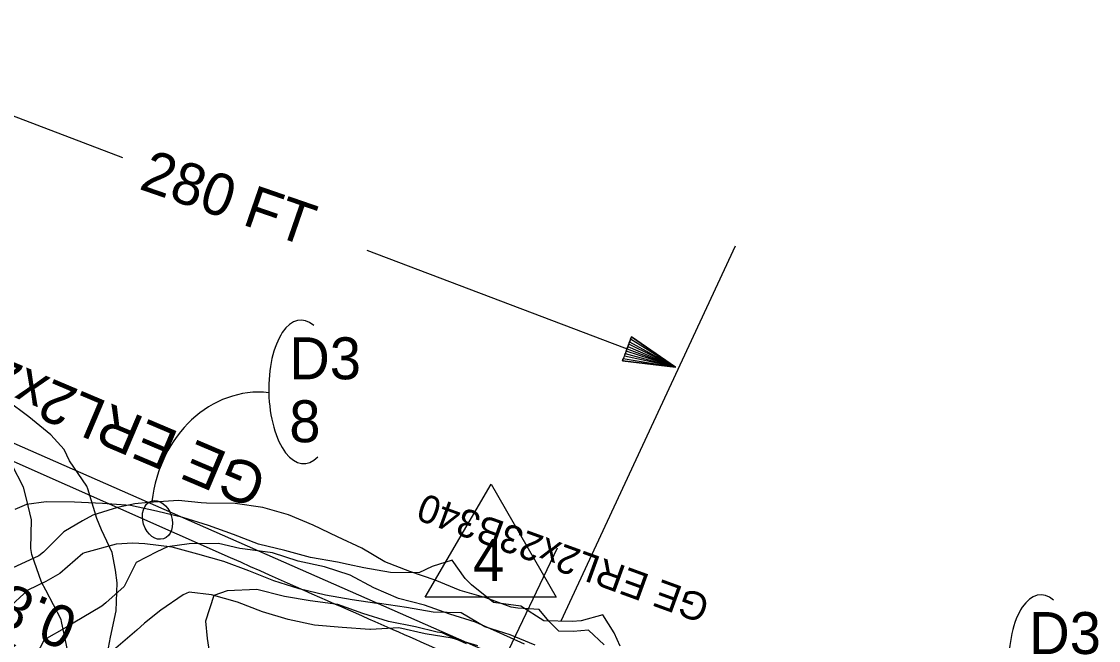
# Model space of a CAD drawing. Extents: x 1638506 to 1658005, y 834807 to 846788.
# Drawn here: x 1639907.1 to 1640215, y 842876.3 to 843053.2 of the extents above; entities that cross this region are included whole.
import ezdxf

# ---------------------------------------------------------------- set-up
doc = ezdxf.new("R2010")
doc.units = 0
for name, color, linetype in [('Default', 7, 'Continuous'), ('Old_Level_1', 7, 'Continuous'), ('Old_Level_2', 7, 'Continuous'), ('Scratch_Level_0', 7, 'Continuous')]:
    doc.layers.add(name, color=color, linetype=linetype)

msp = doc.modelspace()

# ---------------------------------------------------------------- linework, layer by layer
at = {"layer": 'Default'}
for p, q in [((1639833.61, 843053.21), (1639935.97, 843014.38)), ((1640061.33, 842881.89), (1640111.26, 842989.14)), ((1640005.81, 842987.89), (1640094.02, 842954.42)), ((1640057.32, 842865.64), (1639806, 842976.14))]:
    msp.add_line(p, q, dxfattribs=at)
msp.add_lwpolyline([(1640080.18, 842959.67), (1640080.45, 842960.36), (1640094.02, 842954.42), (1640080.69, 842961.01), (1640080.95, 842961.7), (1640094.02, 842954.42), (1640081.22, 842962.39), (1640081.48, 842963.08), (1640094.02, 842954.42), (1640078.92, 842956.19), (1640079.13, 842956.9), (1640094.02, 842954.42), (1640079.44, 842957.58), (1640079.66, 842958.29), (1640094.02, 842954.42), (1640079.92, 842958.98), (1640081.48, 842963.08), (1640078.92, 842956.19), (1640094.02, 842954.42), (1640081.48, 842963.08)], dxfattribs=at)
msp.add_lwpolyline([(1640059.9, 842888.67), (1640022.51, 842888.67), (1640041.34, 842920.94)], close=True, dxfattribs=at)
for centre, major_axis, ratio, start_param, end_param in [((1639987.34, 842947.36), (-0.49, 20.52), 0.466223, 5.884886, 7.853982), ((1639973.99, 842912.79), (-3.78, -34.34), 0.862742, 3.141593, 4.712389), ((1639987.34, 842947.36), (-0.49, 20.52), 0.466223, 1.570796, 3.572354), ((1640198.9, 842868.83), (-0.49, 20.52), 0.466223, 5.884886, 7.853982)]:
    msp.add_ellipse(centre, major_axis=major_axis, ratio=ratio, start_param=start_param, end_param=end_param, dxfattribs=at)
msp.add_ellipse((1639945.93, 842910.76), major_axis=(1.72, -5.4), ratio=0.730797, dxfattribs=at)
at = {"layer": 'Old_Level_1'}
for points in [[(1639901.9, 842853.27), (1639907.42, 842853.8), (1639910.47, 842854.47), (1639919.6, 842857.18), (1639920.08, 842857.33), (1639927.78, 842862.67), (1639931.08, 842869.61), (1639932.55, 842877.22), (1639934.16, 842884.77), (1639934.43, 842892.81), (1639933.89, 842896.44), (1639932.96, 842901.49), (1639929.92, 842907.9), (1639928.62, 842911.21), (1639926.04, 842919.61), (1639925.78, 842920.38), (1639920.81, 842927.62), (1639919.23, 842930.91), (1639915.4, 842935.1), (1639909.14, 842940.26), (1639902.79, 842945.03)], [(1640078.22, 842874.69), (1640076.52, 842878.47), (1640073.32, 842883.59), (1640067.04, 842881.92), (1640064.49, 842881.72), (1640056.42, 842881.9), (1640049.81, 842886.1), (1640042.04, 842887.13), (1640035.74, 842892.18), (1640033.92, 842893.98), (1640030.19, 842899.29), (1640024.44, 842897.43), (1640020.71, 842895.62), (1640012.61, 842895.74), (1640004.95, 842897.06), (1640000.48, 842898), (1639997.41, 842898.7), (1639989.74, 842900), (1639982.33, 842902.01), (1639974.85, 842903.84), (1639967.72, 842906.59), (1639960.51, 842909.17), (1639953.21, 842911.47), (1639945.7, 842913.22), (1639938.19, 842914.93), (1639930.24, 842915.45), (1639930.18, 842915.45), (1639922.25, 842915.88), (1639914.13, 842915.95), (1639908.5, 842915.2), (1639905.17, 842913.7)], [(1640053.91, 842875), (1640046.82, 842877.89), (1640039.53, 842880.23), (1640032.82, 842884.17), (1640024.75, 842884.37), (1640017.1, 842885.71), (1640009.39, 842886.88), (1640008.64, 842886.89), (1640001.63, 842887.94), (1639993.96, 842889.23), (1639986.47, 842891.02), (1639979.18, 842893.35), (1639972.09, 842896.25), (1639964.9, 842898.85), (1639957.52, 842900.95), (1639950.11, 842902.96), (1639942.34, 842903.96), (1639938.87, 842904.15), (1639934.15, 842903.83), (1639925.12, 842901.4), (1639924.56, 842901.21), (1639917.99, 842895.46), (1639913.99, 842893.18), (1639908.84, 842890.65), (1639903.01, 842885.39)], [(1640037.53, 842874.75), (1640030.21, 842876.98), (1640022.51, 842878.2), (1640014.98, 842879.88), (1640006.81, 842879.42), (1640006.67, 842879.42), (1639998.74, 842880), (1639990.85, 842880.69), (1639983.3, 842882.32), (1639975.97, 842884.53), (1639968.83, 842887.28), (1639961.42, 842889.31), (1639955.01, 842890.13), (1639953.31, 842889.39), (1639946.86, 842884.96), (1639942.22, 842881.27), (1639940.05, 842879.3), (1639933.4, 842873.58)]]:
    msp.add_lwpolyline(points, dxfattribs=at)
at = {"layer": 'Old_Level_2'}
msp.add_line((1640060.26, 842902.7), (1639915.76, 842600.41), dxfattribs=at)
msp.add_lwpolyline([(1639966.8, 842899.95), (1639748.06, 842996.94), (1639720.4, 843009.03)], dxfattribs=at)
msp.add_open_spline([(1640158.61, 842819.26), (1640157.59, 842819.64), (1640156.58, 842820.02), (1640154.56, 842820.79), (1640153.54, 842821.17), (1640150.51, 842822.33), (1640144.44, 842824.64), (1640130.31, 842830.13), (1640118.24, 842834.94), (1640094.16, 842844.7), (1640078.16, 842851.39), (1640030.3, 842871.79), (1639998.56, 842885.87), (1639966.8, 842899.95)], degree=3, dxfattribs=at)
at = {"layer": 'Scratch_Level_0'}
for points in [[(1639904.44, 842848.57), (1639909.98, 842852.6), (1639915.75, 842858.47), (1639919.09, 842865.36), (1639920.33, 842873.14), (1639918.51, 842881.76), (1639918.41, 842882.27), (1639913.97, 842890.65), (1639912.79, 842892.96), (1639910, 842900.88), (1639909.75, 842902.56), (1639909.93, 842910.79), (1639908.45, 842916.82), (1639907.61, 842920.08), (1639904.31, 842926.64)], [(1640073.63, 842875.09), (1640069.16, 842879.22), (1640064.75, 842878.86), (1640060.74, 842878.96), (1640057.87, 842881.78), (1640055.07, 842885.2), (1640049, 842885.54), (1640047.05, 842885.87), (1640039.86, 842888.51), (1640032.44, 842890.61), (1640025.36, 842893.52), (1640018.11, 842896), (1640010.98, 842898.79), (1640004.33, 842902.7), (1639997.38, 842905.91), (1639990.5, 842909.27), (1639983.45, 842912.25), (1639976.03, 842914.35), (1639968.17, 842915.41), (1639959.93, 842915.57), (1639958.42, 842915.64), (1639951.94, 842916.33), (1639943.4, 842915.79), (1639939.51, 842915.35), (1639934.48, 842914.34), (1639927.47, 842912.15), (1639924.54, 842910.49), (1639919.17, 842907.36), (1639913.38, 842901.51), (1639912, 842900.52), (1639904.37, 842897.02)], [(1640050.85, 842875.24), (1640043.88, 842878.41), (1640036.89, 842881.51), (1640029.56, 842883.82), (1640022.33, 842886.37), (1640014.86, 842888.34), (1640007.82, 842891.34), (1640001.07, 842895.01), (1639993.74, 842897.32), (1639986.12, 842898.97), (1639978.82, 842901.33), (1639970.97, 842902.41), (1639969.48, 842902.64), (1639963.35, 842904.05), (1639954.98, 842903.89), (1639948.85, 842903.09), (1639945.72, 842901.65), (1639939.87, 842898.58), (1639936.46, 842891.72), (1639931.2, 842887.02), (1639930, 842886.15), (1639921.88, 842881.29), (1639919.97, 842880.13), (1639913.52, 842876.52), (1639909.98, 842869.71)], [(1640034.29, 842875.38), (1640027.31, 842878.51), (1640025.91, 842878.71), (1640019.7, 842880.17), (1640012.04, 842881.7), (1640004.69, 842883.97), (1639997.5, 842886.59), (1639989.61, 842887.59), (1639982.25, 842888.92), (1639981.9, 842889), (1639974.38, 842890.87), (1639965.9, 842890.46), (1639962.07, 842889.17), (1639959.68, 842881.87), (1639960.13, 842876.87), (1639960.69, 842873.14)]]:
    msp.add_lwpolyline(points, dxfattribs=at)

# ---------------------------------------------------------------- texts
at = {"layer": 'Default'}
msp.add_text('280 FT', height=12, rotation=340.967, dxfattribs=at).set_placement((1639940.34, 843005.46))
for s, height, p in [('D3', 11.995, (1639983.63, 842950.96)), ('8', 12, (1639983.63, 842932.96)), ('4', 12, (1640036.16, 842893.28)), ('D3', 11.995, (1640195.19, 842872.43))]:
    msp.add_text(s, height=height, dxfattribs=at).set_placement(p)
at = {"layer": 'Old_Level_1'}
msp.add_text('GE ERL2x23B340', height=8, rotation=160, dxfattribs=at).set_placement((1640104.37, 842888.63))
at = {"layer": 'Scratch_Level_0'}
for s, p in [('GE ERL2x23C340', (1639978.02, 842924.85)), ('0.8, 1.0, 1.2', (1639923.93, 842884.33)), ('0.1, 0.2, 0.4,', (1639926.63, 842863.63))]:
    msp.add_text(s, height=12, rotation=157.0176, dxfattribs=at).set_placement(p)

doc.saveas('drawing.dxf')
